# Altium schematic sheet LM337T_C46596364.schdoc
size 127 x 101 mm
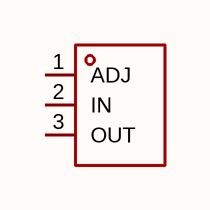
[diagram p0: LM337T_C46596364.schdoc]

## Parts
U?  lm337t_c46596364  [TO-220-3_L10.0-W4.5-P2.54-L-1]  (value not drawn)

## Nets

Not connected (* = marked no-connect by the designer): U? 1(ADJ) 2(IN) 3(OUT)

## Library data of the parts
U? = lm337t_c46596364: 输出极性:负极;工作电压:-;输出电压:1.25V~37V;输出电流:1.5A;电源纹波抑制比(PSRR):77dB;输出类型:可调;; Manufacturer: JSMSEMI(杰盛微); ManufacturerPart: LM337T; AddInBom: yes; ModelId: f3b81a431813461aaa6f5a84087f9609; ModelTransform: 393.7,175.23587,0,0,0,0,0,16.417,-196.85; Output Configuration: 负极; Output Current: 1.5A; Power Supply Rejection Ratio (PSRR): 77dB; Noise: 0.003%Vout; Output Type: 可调; Number of Outputs: 1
